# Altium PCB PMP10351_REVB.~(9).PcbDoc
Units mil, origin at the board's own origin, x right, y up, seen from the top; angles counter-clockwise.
Board outline 2350 x 1500 mil, 2 copper layers (Top Layer, Bottom Layer), stack 62 mil thick; 34 components, 23 nets, 80 pads, 5 vias.
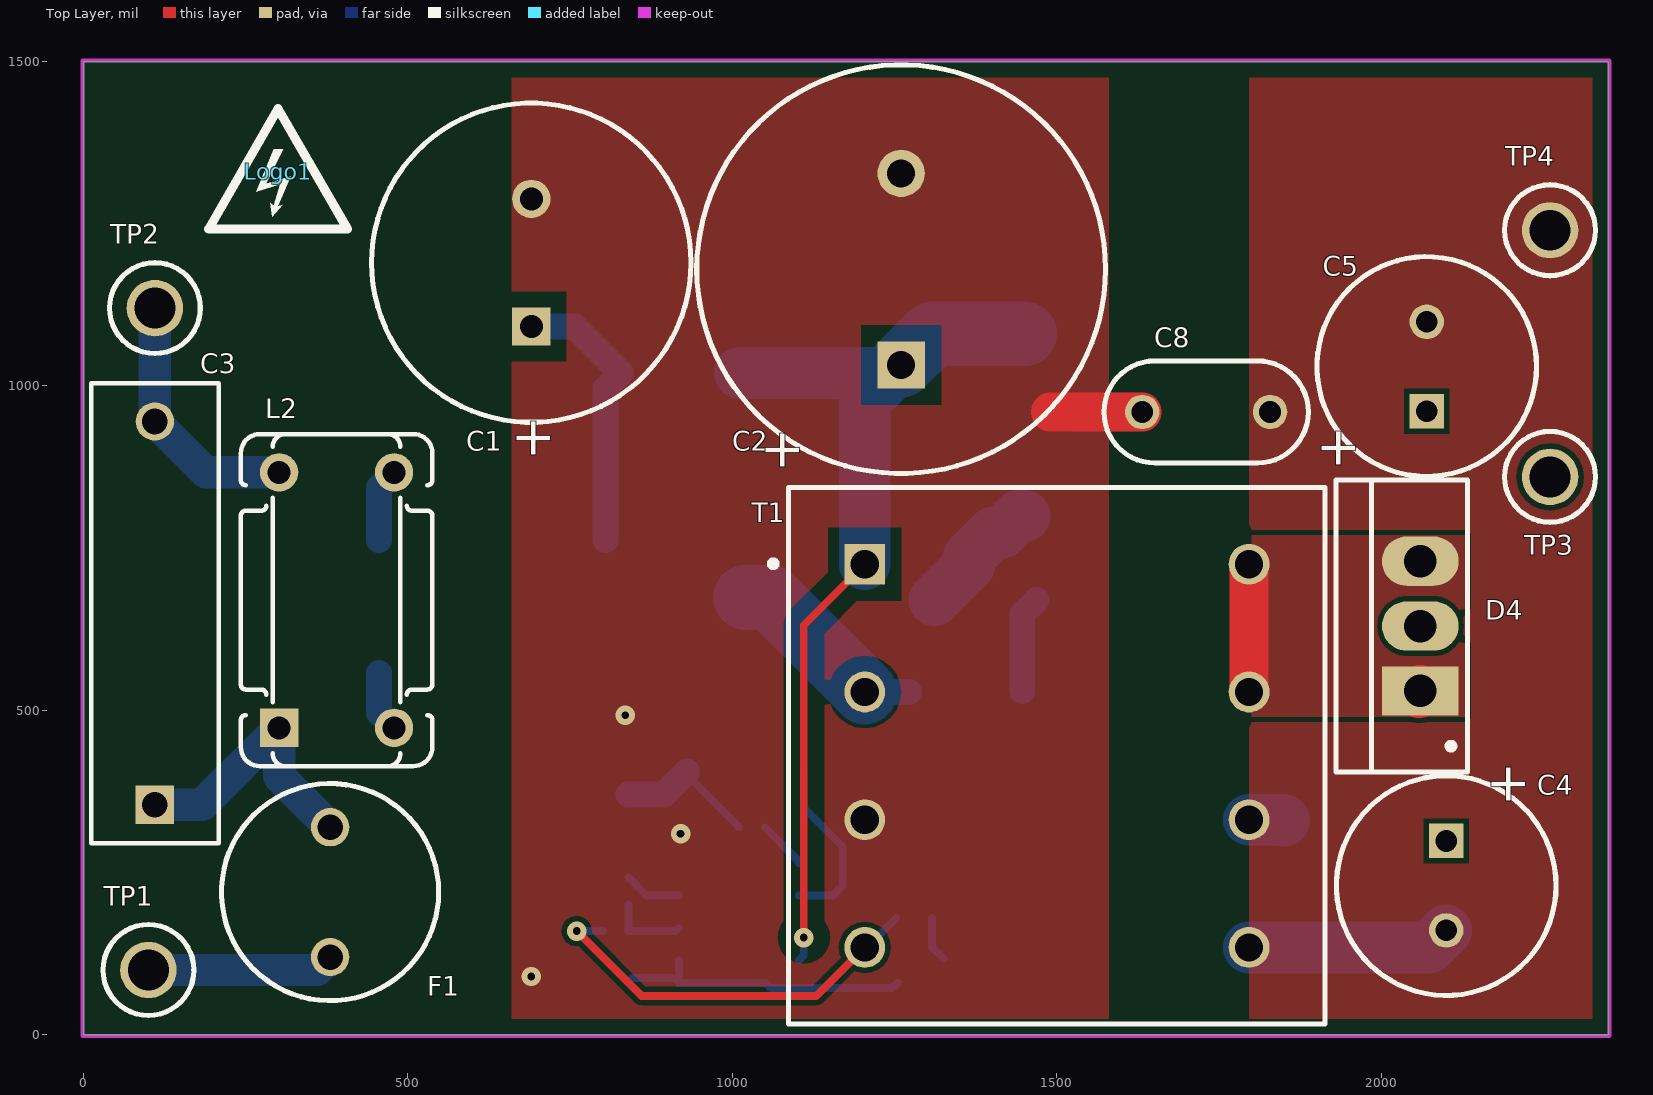
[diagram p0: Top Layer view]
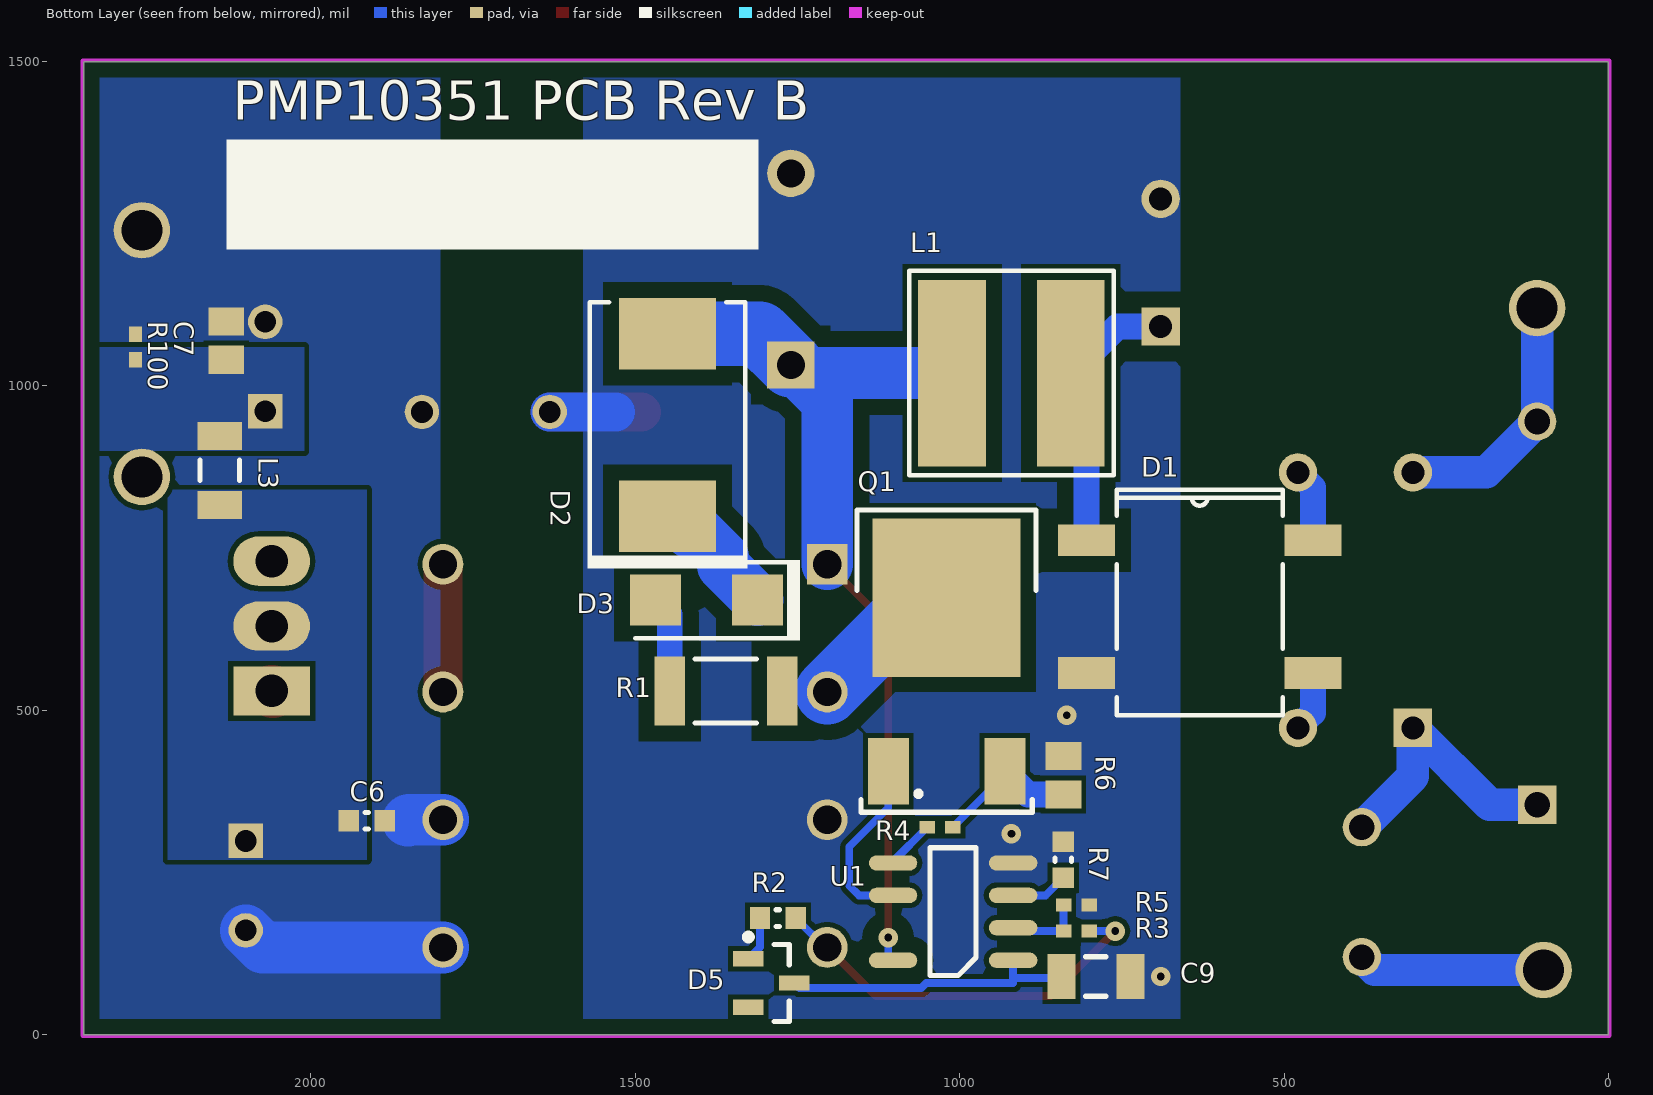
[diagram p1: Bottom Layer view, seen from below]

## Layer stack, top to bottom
Top Solder: solder mask 0.4, Solder Resist, Dk 3.5
Top Layer: signal copper 1.4
Dielectric1: core 59.2, FR-4, Dk 4.8
Bottom Layer: signal copper 1.4
Bottom Solder: solder mask 0.4, Solder Resist, Dk 3.5

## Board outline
0,0 2350,0 2350,1500 0,1500

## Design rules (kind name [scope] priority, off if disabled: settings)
AcuteAngle [All] p1: minimum=1.00000000000000E+0000 checktracksonly=FALSE
AssemblyTestPointUsage [All] p1: valid=2
Clearance "Schematic Clearance Constraint_4" [InNet('NetC1_1')] p1: gap=25
Clearance "Schematic Clearance Constraint_3" [InNet('NetC2_1')] p2: gap=25
Clearance "Schematic Clearance Constraint_2" [InNet('NetD2_1')] p3: gap=25
Clearance "Schematic Clearance Constraint_1" [InNet('NetD3_2')] p4: gap=25
Clearance "Schematic Clearance Constraint" [InNet('NetQ1_4')] p5: gap=24
Clearance Clearance_Keepouts [((IsTrack Or IsArc) And Not InPoly) And IsFree and IsKeepOut vs ((IsTrack Or IsArc) And Not InPoly) And IsFree and IsKeepOut] p6: gap=0
Clearance Clearance_BoardEdge_MountingHoles [OnCopper and InComponentClass('Mounting Holes') vs IsKeepOut] p7: gap=25
Clearance Clearance_BoardEdge_Poly [OnCopper and InPoly vs IsKeepOut] p8: gap=25
Clearance Clearance_BoardEdge [OnCopper and Not InComponentClass('Logo') and not InComponentClass('FiducialMark') and not InRegion(1000,500,4000,800) and Not IsKeepout vs IsKeepOut] p9: gap=15
Clearance Clearance_Poly [InPolygon] p10: gap=8
Clearance [All] p11: gap=7.87
ComponentClearance ComponentClearance_MountingHoles_FiducialMarks [InComponentClass('Mounting Holes') vs InComponentClass('FiducialMark')] p1: gap=15 collisioncheckmode=3 verticalgap=10 showdistances=FALSE
ComponentClearance ComponentClearance_Shunt [InComponentClass('Header') vs InComponentClass('Shunt')] p2: gap=0 collisioncheckmode=3 verticalgap=0 showdistances=FALSE
ComponentClearance ComponentClearance_Logo [InComponentClass('Logo')] p3: gap=15 collisioncheckmode=3 verticalgap=10 showdistances=FALSE
ComponentClearance ComponentClearance_ScrewToNut [(HasFootprint('NY PMS 440 0025 PH')) vs (HasFootprint('Keystone_1902C'))] p4: gap=5 collisioncheckmode=3 verticalgap=10 showdistances=FALSE
ComponentClearance ComponentClearance_MountingHoles [InComponentClass('Mounting Holes')] p5: gap=15 collisioncheckmode=3 verticalgap=100000 showdistances=FALSE
ComponentClearance ComponentClearance_SmallPassives [HasFootprint('0201*') or HasFootprint('0402*') or HasFootprint('0508') or HasFootprint('0603*') or HasFootprint('0612') or HasFootprint('0805*') or HasFootprint('0815*') or HasFootprint('0830*') or HasFootprint('1206*') or HasFootprint('1210*') or HasFootprint('1808*') or HasFootprint('1812*') or HasFootprint('1825*') or HasFootprint('2010*') or HasFootprint('2220*') or HasFootprint('2225*') or HasFootprint('2512*') or HasFootprint('2728*') or HasFootprint('3518*') vs HasFootprint('0201*') or HasFootprint('0402*') or HasFootprint('0508') or HasFootprint('0603*') or HasFootprint('0612') or HasFootprint('0805*') or HasFootprint('0815*') or HasFootprint('0830*') or HasFootprint('1206*') or HasFootprint('1210*') or HasFootprint('1808*') or HasFootprint('1812*') or HasFootprint('1825*') or HasFootprint('2010*') or HasFootprint('2220*') or HasFootprint('2225*') or HasFootprint('2512*') or HasFootprint('2728*') or HasFootprint('3518*')] p6: gap=15 collisioncheckmode=3 verticalgap=10 showdistances=FALSE
ComponentClearance ComponentClearance_THtoSMT [IsThruComponent vs IsSMTComponent] p7: gap=15 collisioncheckmode=3 verticalgap=30 showdistances=FALSE
ComponentClearance ComponentClearance_THtoTH [IsThruComponent vs IsThruComponent] p8: gap=15 collisioncheckmode=3 verticalgap=30 showdistances=FALSE
ComponentClearance [All] p9: gap=15 collisioncheckmode=3 verticalgap=10 showdistances=FALSE
DiffPairsRouting [All] p1: maxlimit=100 minlimit=10 mostfreqgap=10 toplayer_minwidth=15 toplayer_maxwidth=15 toplayer_prefwidth=15 bottomlayer_minwidth=15 bottomlayer_maxwidth=15 bottomlayer_prefwidth=15 maxuncoupledlength=1000
FabricationTestPointUsage TestPointUsage [All] p1: valid=2 allowmultiple=FALSE
FabricationTestpoint Testpoint [All] p1: side=3 testpointundercomponent=TRUE minsize=40 maxsize=100 preferedsize=60 minholesize=0 maxholesize=40 preferedholesize=32 testpointgrid=1 allowsidetop=TRUE allowsidebottom=TRUE usegrid=TRUE gridtolerance=0.01
FanoutControl Fanout_LCC [IsLCC] p1: bgadir=Out bgaviamode=Centered fanoutstyle=Auto fanoutdirection=Alternating viagrid=1 // Fanout_LCC (Default Rule)
FanoutControl Fanout_BGA [IsBGA] p2: bgadir=Out bgaviamode=Centered fanoutstyle=Auto fanoutdirection=Alternating viagrid=1 // Fanout_BGA (Default Rule)
FanoutControl Fanout_Default [All] p4: bgadir=Out bgaviamode=Centered fanoutstyle=Auto fanoutdirection=Alternating viagrid=1 // Fanout_Default (Default Rule)
FanoutControl Fanout_Small [(CompPinCount < 5)] p5: bgadir=Out bgaviamode=Centered fanoutstyle=Auto fanoutdirection=OutThenIn viagrid=1 // Fanout_Small (Default Rule)
HoleSize [All] p1: absolutevalues=TRUE maxlimit=251 minlimit=8 maxpercent=80.000 minpercent=20.000
MinimumAnnularRing MinimumAnnularRing_ThermalPadVias [IsVia and InAnyComponent] p1: minimumring=5.91
MinimumAnnularRing [All] p2: minimumring=9
MinimumSolderMaskSliver MinimumSolderMaskSliver_Logo [InComponentClass('Logo') vs InComponentClass('Logo')] p1: minsoldermaskwidth=0.7
MinimumSolderMaskSliver [All] p2: minsoldermaskwidth=0
PlaneConnect [All] p1: planeconnectstyle=Relief reliefexpansion=10 reliefentries=4 reliefconductorwidth=10 reliefairgap=10
PolygonConnect [All] p1: connectstyle=Direct reliefconductorwidth=10 reliefentries=4 polygonreliefangle="90 Angle" airgapwidth=10
RoutingVias ThermalPadVias [IsVia and InAnyComponent] p1: holewidth=7.87 width=19.68 viastyle="Through Hole" minholewidth=7.87 minwidth=19.68 maxholewidth=12.99 maxwidth=23.62
RoutingVias [All] p2: holewidth=16 width=34 viastyle="Through Hole" minholewidth=7.87 minwidth=26 maxholewidth=40 maxwidth=65
SilkToBoardRegionClearance [Not ((IsComment or IsDesignator) And (Hide <> 'False')) and not InRegion(1000,500,4000,800)] p1:
SilkToSilkClearance SilkToSilkClearance_Pb-FreeLogo [(HasFootprint('Pb-Free_Overlay_Medium') OR HasFootprint('Pb-Free_Overlay_Small')) vs (HasFootprint('Pb-Free_Overlay_Medium') OR HasFootprint('Pb-Free_Overlay_Small'))] p1: silktosilkclearance=0
SilkToSilkClearance [All] p2: silktosilkclearance=0
SilkToSolderMaskClearance "Silk to Solder Mask Opening" [All] p1: minsilkscreentomaskgap=0 clearancetoexposedcopper=FALSE
SolderMaskExpansion [All] p1: expansion=1.97
UnpouredPolygon [All] p1: allowunpoured=FALSE
Width [All] p1: maxlimit=100 minlimit=6 preferedwidth=10 checkconnectedcopper=TRUE
14 further rules are at their usual default settings.

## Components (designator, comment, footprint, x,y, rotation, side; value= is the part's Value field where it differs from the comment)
C1 "EEUED2G150" CAPPR5-12.5X20 690,1190 r90 top
C2 "EEUED2G330S" CAPPR7.5-16X20 1260,1180 r90 top
C3 "B32922C3104M" B32922_10.5mm 110,650 r90 top
C4 "16ZLG470MEFC8X16" ZLG_800x1600 2100,230 r270 top
C5 "16ZLG470MEFC8X16" ZLG_800x1600 2070,1030 r90 top
C6 "GRM188R61E105KA12D" 0603L 1913.39,330 r180 bottom
C7 "GRM21BR61E106MA73" 0805L 2130,1070 r90 bottom
C8 "DE2E3KY222MA2BM01" CAPRD500W60D800H850 1730,960 r180 top
C9 "GRM319R61H475KA12" 1206L 790,90 r180 bottom
D1 "DF1506S-T" DF-S 630,660 r180 bottom
D2 "SMCJ100A" SMC 1450,940 r90 bottom
D3 "MURA160T3G" SMA 1390,670 r0 bottom
D4 "VF40100C-E3/4W" TO-220AB 2060,630 r90 top
D5 "BAS21-TP" SOT-23L 1290,80 r180 bottom
F1 "37212000001" FUSE_372 380,220 r270 top
L1 "CDRH6D28NP-330NC" CDRH6D28 920,1020 r0 bottom
L2 "744821240" WE-CMB_XS 390,670 r90 top
L3 "HI1206T500R-10" 1206L 2140,870 r90 bottom
Logo1 "DANGER HIGH VOLTAGE" IEC_HighVoltage_Small 300,1330 r0 top
Q1 "TK5P60W_RVQ" DPAK 1020,540 r90 bottom
R1 "CRCW201024R0JNEF" 2010L 1360,530 r0 bottom
R2 "CRCW060320R0JNEA" 0603L 1280,180 r0 bottom
R3 "CRCW040282K5FKED" 0402L 820,160 r180 bottom
R4 "CRCW04021K00FKED" 0402L 1030,320 r0 bottom
R5 "CRCW040223K7FKED" 0402L 820,200 r0 bottom
R6 "CRM0805-FX-R510ELF" 0805L 840,400 r270 bottom
R7 "N/A" 0603L 840,270 r270 bottom
R100 "CRCW04024K99FKED" 0402L 2270,1060 r90 bottom
T1 "G144071LF" GCI_G144071LF 1500,430 r0 top
TP1 "5012" Keystone5012 100,100 r0 top
TP2 "5012" Keystone5012 110,1120 r0 top
TP3 "5010" Keystone5010 2260,860 r0 top
TP4 "5011" Keystone5011 2260,1240 r0 top
U1 "UCC28713D" D0007A_L 1010,190 r0 bottom

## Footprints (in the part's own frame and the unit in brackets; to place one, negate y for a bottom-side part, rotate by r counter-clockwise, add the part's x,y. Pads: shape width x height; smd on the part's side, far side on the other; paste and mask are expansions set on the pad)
0402L [mm] "0402 from SM-752 data"
  rect 0.6x0.5 smd: 1(-0.5,0) 2(0.5,0)
  body extent -0.55,-0.3 0.55,0.3, height 0.6
0603L [mm] "0603 from SM-752 data"
  rect 0.8x0.85 smd: 1(-0.7,0) 2(0.7,0)
  silkscreen extent -0.07,-0.33 0.07,0.33, body extent -0.87,-0.47 0.87,0.47, height 0.85
0805L [mm] "0805 from SM-752 data"
  rect 1.1x1.4 smd: 1(-0.75,0) 2(0.75,0)
  body extent -1.1,-0.72 1.1,0.72, height 1.1
1206L [mm] "1206 from SM-752 data"
  rect 1.1x1.75 smd: 1(-1.35,0) 2(1.35,0)
  silkscreen extent -0.4,-0.77 0.4,0.77, body extent -1.7,-0.9 1.7,0.9, height 1.35
2010L [mm]
  rect 1.2x2.7 smd: 1(-2.2,0) 2(2.2,0)
  silkscreen extent -1.2,-1.25 1.2,1.25, body extent -2.73,-1.45 2.73,1.45, height 1.66
B32922_10.5mm [mm] "Epcos film capacitors, 15mm spacing"
  rect 1.5x1.5 hole 1: 1(-7.5,0)
  round 1.5 hole 1: 2(7.5,0)
  silkscreen extent -9,-2.5 9,2.5, body extent -9,-2.5 9,2.5, height 10.5
CAPPR5-12.5X20 [mm] "Capacitor, Electrolytic, Radial; Body 12.5 x 20 mm (Dia.xH typ); Pin Spacing 5 mm (typ)"
  rect 1.5x1.5 hole 0.9: 1(-2.5,0)
  round 1.5 hole 0.9: 2(2.5,0)
  silkscreen extent -6.25,-6.25 6.25,6.25, body extent -6.01,-6.01 6.01,6.01, height 22
CAPPR7.5-16X20 [mm] "Capacitor, Electrolytic, Radial; Body 16 x 20 mm (Dia.xH typ); Pin Spacing 7.5 mm (typ)"
  rect 1.85x1.85 hole 1.1: 1(-3.75,0)
  round 1.85 hole 1.1: 2(3.75,0)
  silkscreen extent -8,-8 8,8, body extent -8.01,-8.01 8.01,8.01, height 22
CAPRD500W60D800H850 [mm] "RADIAL CAPACITOR"
  round 1.35 hole 0.85: 1(-2.5,0) 2(2.5,0)
  silkscreen extent -4,-2 4,2, body extent -3.97,-2.5 4,2.5, height 10.99
CDRH6D28 [mm] "Sumida reommended land pattern"
  rect 2.65x7.3 smd: 1(-2.325,0) 2(2.325,0)
  silkscreen extent -4,-4 4,4, body extent -3.5,-3.5 3.5,3.5, height 3
D0007A_L [mm] "SOIC, 7-Leads, Body 4.9x3.9mm, Pitch 1.27mm, IPC High Density"
  oval 1.9x0.6 smd: 1(-2.35,1.905) 2(-2.35,0.635) 3(-2.35,-0.635) 4(-2.35,-1.905) 5(2.35,-1.905) 6(2.35,-0.635) 8(2.35,1.905)
  silkscreen extent -0.9,-2.5 0.9,2.5, body extent -3,-2.5 3,2.5, height 1.54
DF-S [mil] "Diodes Inc. recommended land pattern per ap02001.pdf rev 30"
  rect 88x49 smd: 1(-174.5,102.36) 2(-174.5,-102.36) 3(174.5,-102.36) 4(174.5,102.36)
  silkscreen extent -128,-168 128,180, body extent -205,-168 205,168, height 108
DPAK [mm] "D-PAK, 3-Pads, Body 6.22x6.73mm (max), TO-252AA using nominal STEP model"
  rect 2.6x1.6 smd: 1(-3.4,2.28) 3(-3.4,-2.28)
  rect 6.2x5.8 smd paste-2.9: 4(3.4,0)
  silkscreen extent -5,-3.5 6.83,3.5, body extent -3.86,-3.29 5.84,3.29, height 2.48
FUSE_372 [mm] "LITTELFUSE"
  round 1.5 hole 1: 1(-2.54,0) 2(2.54,0)
  silkscreen extent -4.25,-4.25 4.25,4.25, body extent -4.26,-4.26 4.26,4.26, height 8
GCI_G144071LF [mm] "THD, 8-Leads, Body 21x21mm, Pitch 5mm"
  rect 1.6x1.6 hole 1.1: 1(-7.52,7.5)
  round 1.6 hole 1.1: 2(-7.52,2.5) 3(-7.52,-2.5) 4(-7.52,-7.5) 5(7.52,-7.5) 6(7.52,-2.5) 7(7.52,2.5) 8(7.52,7.5)
  silkscreen extent -11.22,-10.5 10.5,10.5, body extent -10.5,-10.5 10.5,10.5, height 16.5
IEC_HighVoltage_Small [mil]
  silkscreen extent -107,-88 107,97
Keystone5010 [mil] "Keystone Multipurpose loops"
  round 87 hole 63: 1(0,0)
  silkscreen extent -70,-70 70,70, body extent -63,-63 63,62, height 319
Keystone5011 [mil] "Keystone Multipurpose loops"
  round 87 hole 63: 1(0,0)
  silkscreen extent -70,-70 70,70, body extent -63,-63 63,62, height 319
Keystone5012 [mil] "Keystone Multipurpose loops"
  round 87 hole 63: 1(0,0)
  silkscreen extent -70,-70 70,70, body extent -63,-63 63,62, height 319
SMA [mm] "Molded Diode, 2-Leads, Body 4.3x2.6mm, IPC Medium Density, based on OnSemi component dimensions and land pattern"
  rect 2x2 smd: 1(-2,0) 2(2,0)
  silkscreen extent -3.66,-1.57 2.79,1.57, body extent -2.6,-1.3 2.6,1.3, height 2.42
SMC [mil] "Molded Diode, 2-Leads, Body 6.9x5.8mm, IPC Medium Density, based on OnSemi component dimensions and land patterns"
  rect 110x150 smd: 1(-140.49,0) 2(140.49,0)
  silkscreen extent -221,-123 189,124, body extent -156,-116 156,116, height 91
SOT-23L [mm] "SOT23, 3-Leads, Body 2.9x1.3mm, Pitch 0.95mm, Lead Span 2.5mm, IPC High Density"
  rect 1.2x0.6 smd: 1(-0.9,0.95) 2(-0.9,-0.95) 3(0.9,0)
  silkscreen extent -1.02,-1.5 0.7,1.92, body extent -1.16,-1.45 1.21,1.45, height 1
TO-220AB [mil] "Copied from Altium's version of TO3B"
  rect 76x118.11 hole 50: 1(-100,0)
  oval 76x118.11 hole 50: 2(0,0) 3(100,0)
  silkscreen extent -225,-73 225,130, body extent -221,-59 221,126, height 765
WE-CMB_XS [mm] "WE-CMB Series Size XS"
  rect 1.5x1.5 hole 0.9: 1(-5,2.25)
  round 1.5 hole 0.9: 2(-5,-2.25) 3(5,-2.25) 4(5,2.25)
  silkscreen extent -6.5,-3.75 6.5,3.75, body extent -6.5,-3.75 6.5,3.75, height 16.24
ZLG_800x1600 [mm] "TH, 2-Leads, Body 8x16mm"
  rect 1.35x1.35 hole 0.85: 1(-1.75,0)
  round 1.35 hole 0.85: 2(1.75,0)
  silkscreen extent -4.3,-4.3 4.3,4.3, body extent -4.22,-4.34 4.24,4.14, height 17.51

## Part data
C1: "CAP, AL, 15uF, 400V, +/-20%, 1.909859 ohm, TH"
C2: "CAP, AL, 33 µF, 400 V, +/- 20%, 0.868117 ohm, TH"
C3: "CAP, Film, 0.1 µF, 630 V, +/- 20%, TH"
C4 C5: "CAP, AL, 470 µF, 16 V, +/- 20%, 0.028 ohm, TH"
C6: "CAP, CERM, 1 µF, 25 V, +/- 10%, X5R, 0603"
C7: "CAP, CERM, 10 µF, 25 V, +/- 20%, X5R, 0805"
C8: "CAP, CERM, 2200pF, 250V, +/-20%, KY, Radial D8x5mm"
C9: "CAP, CERM, 4.7 µF, 50 V, +/- 10%, X5R, 1206"
D1: "Diode, Switching-Bridge, 600V, 1.5A, DF-S"
D2: "Diode, TVS, Uni, 100V, 1500W, SMC"
D3: "Diode, Ultrafast, 600V, 1A, SMA"
D4: "Diode, Schottky, 100V, 20A, TH"
D5: "Diode, P-N, 200V, 200A, SOT-23"
F1: library part 37215000001, "Fuse, 2A, 250V, TH"
L1: "Inductor, Shielded Drum Core, Ferrite, 33uH, 0.97A, 0.165 ohm, SMD"
L2: "Coupled inductor, 4000uH, 1.5A, 0.14 ohm, +/-30%, TH"
L3: "Ferrite Bead, 50 ohm @ 100MHz, 6A, 1206"
Logo1: library part IEC_HighVoltage, "IEC 61010-1 High Voltage Warning"
Q1: "MOSFET, N-CH, 600V, 5.4A, DPAK"
R1: "RES, 24 ohm, 5%, 0.75W, 2010"
R2: "RES, 20, 5%, 0.1 W, 0603"
R3: "RES, 82.5 k, 1%, 0.063 W, 0402"
R4: "RES, 1.00 k, 1%, 0.063 W, 0402"
R5: "RES, 23.7 k, 1%, 0.063 W, 0402"
R6: "RES, 0.51 ohm, 1%, 0.25W, 0805"
R7: library part CRCW06030000Z0EA, "Do Not Populate"
R100: "RES, 4.99 k, 1%, 0.063 W, 0402"
T1: "Transformer, 400 uH, TH"
TP1 TP2: "Test Point, Multipurpose, White, TH"
TP3: "Test Point, Multipurpose, Red, TH"
TP4: "Test Point, Multipurpose, Black, TH"
U1: "Constant-Voltage, Constant-Current Controller With Primary-Side Regulation, D0007A"

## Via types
v1: diameter 30, hole 12, Top Layer to Bottom Layer, 5 vias

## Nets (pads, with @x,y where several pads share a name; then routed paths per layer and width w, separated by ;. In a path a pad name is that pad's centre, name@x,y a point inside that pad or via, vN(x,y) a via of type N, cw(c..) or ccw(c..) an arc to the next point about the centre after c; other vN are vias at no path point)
GND: C4.2 C5.2 C6.2 C7.2 C8.1 R100.2 T1.5 T1.6 TP4.1 | length 369.5
  Bottom Layer w80: T1.5 2073.62,134.72 C4.2 ; T1.6 1848.43,331.57 1850,330
NetC1_1: C1.1 D1.1 L1.1 | length 435.7
  Bottom Layer w40: C1.1 756.89,1091.57 L1.1 804.5,996.04 D1.1
NetC2_1: C2.1 D2.2 L1.2 T1.1 U1.8 | length 1428.6
  Top Layer w12: v1(1110,150) 1110,631.34 T1.1
  Bottom Layer w12: U1.8 1110,122.48 v1(1110,150)
  Bottom Layer w50: C2.1@1247.64,1020 C2.1
  Bottom Layer w80: L1.2 1247.64,1020 1203.94,976.3 T1.1
  Bottom Layer w100: C2.1 1308.13,1080.49 D2.2
NetC3_1: C3.1 F1.1 L2.1 | length 426.2
  Bottom Layer w50: C3.1 182.99,354.72 L2.1 301.42,398.58 F1.1
NetC3_2: C3.2 L2.4 TP2.1 | length 398.6
  Bottom Layer w50: TP2.1 C3.2 188.43,866.85 L2.4
NetC4_1: C4.1 C6.1 D4.2 L3.1
NetC5_1: C5.1 C7.1 L3.2 R100.1 TP3.1
NetC9_1: C9.1 D5.3 U1.1 | length 450.4
  Bottom Layer w12: C9.1@845.67,87.48 917.48,87.48 ; U1.1 917.48,87.48 ; D5.3 1246.76,72.19 1059.2,72.19 1051.39,80 917.48,80 917.48,87.48
NetD1_3: D1.3 L2.2 | length 94
  Bottom Layer w40: D1.3 455.5,496.23 L2.2
NetD1_4: D1.4 L2.3 | length 114
  Bottom Layer w40: D1.4 455.5,843.77 L2.3
NetD2_1: D2.1 D3.1 | length 200.1
  Bottom Layer w80: D3.1 1364.37,723.11 1364.37,736.29 1402.45,774.37 1415.63,774.37 1440.77,799.51 D2.1
NetD3_2: D3.2 R1.2 | length 149.2
  Bottom Layer w40: R1.2 1446.61,647.87 D3.2
NetD4_1: D4.1 D4.3 T1.7 T1.8 | length 199.1
  Top Layer w60: T1.7 T1.8
  Top Layer w80: D4.1@2058.43,528.43 D4.1
NetD5_1: D5.1 R2.2 | length 70
  Bottom Layer w12: R2.2 1307.56,135.28 D5.1
NetF1_2: F1.2 TP1.1 | length 288.3
  Bottom Layer w50: TP1.1 360,100 F1.2
NetQ1_1: Q1.1 U1.6 | length 274.8
  Bottom Layer w12: U1.6 1155,215 1170,230 1170,290 1109.76,350.24 Q1.1
NetQ1_3: Q1.3 R4.1 R6.2 | length 224.3
  Bottom Layer w12: Q1.3 930.24,400.08 R4.1
  Bottom Layer w40: R6.2 894.57,370.47 Q1.3
NetQ1_4: Q1.4 R1.1 T1.2 | length 312.1
  Bottom Layer w40: T1.2 R1.1@1271.81,528.43
  Bottom Layer w100: Q1.4 1058.5,673.86 T1.2
NetR2_1: R2.1 R3.2 T1.4 | length 623.9
  Top Layer w12: v1(760,160) 860,60 1129.21,60 T1.4
  Bottom Layer w12: v1(760,160) R3.2 ; T1.4 1207.17,134.72 R2.1
NetR3_1: R3.1 R5.2 U1.2 | length 119.9
  Bottom Layer w12: R5.2 R3.1 912.48,160 U1.2
NetR4_2: R4.2 U1.5 | length 76.9
  Bottom Layer w12: R4.2 1102.52,267.17 U1.5
NetR7_2: R7.2 U1.3 | length 88.8
  Bottom Layer w12: R7.2 867.44,215 U1.3
PGND: C1.2 C2.2 C8.2 C9.2 D1.2 R5.1 R6.1 R7.1 T1.3 U1.4 | length 243.1
  Top Layer w60: 1490,960 C8.2
  Bottom Layer w60: 1530,960 C8.2
  other v1: 690,90 920,310 834.73,492.48
pads on no net: D5.2

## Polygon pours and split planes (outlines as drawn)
NetD4_1 on Top Layer "Top Layer-D4" (solid, remove dead copper, pour order 10): 1800,770 2130,770 2130,490 1800,490
GND on Top Layer "Top Layer-GND" (solid, remove dead copper, pour order 11): 1796.07,10 2340,10 2340,1500 1796.07,1500
PGND on Top Layer "Top Layer-PGND" (solid, remove dead copper, pour order 12): 660,10 1580,10 1580,1490 660,1490
GND on Bottom Layer "Bottom Layer-GND" (solid, remove dead copper, pour order 15): 1800,1500 1800,10 2340,10 2340,1500
NetC5_1 on Bottom Layer "Bottom Layer-VOUT" (solid, remove dead copper, pour order 14): 2010,1060 2010,900 2340,900 2340,1060
NetC4_1 on Bottom Layer "Bottom Layer-VOUT1" (solid, remove dead copper, pour order 13): 1913.39,840 1913.39,270 2220,270 2220,840
PGND on Bottom Layer "Bottom Layer-PGND" (solid, remove dead copper, pour order 9): 660,20 1579.92,20 1579.92,1500 660,1500

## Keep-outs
Keep-Out Layer:
  lines w5: -2.5,0 ccw(c0,0) 0,-2.5 ; -2.5,0 ccw(c0,0) 0,-2.5 ; -2.5,0 -2.5,1500 ; -2.5,1500 cw(c0,1500) 0,1502.5 ; -2.5,1500 cw(c0,1500) 0,1502.5 ; 0,-2.5 2350,-2.5 ; 0,1502.5 2350,1502.5 ; 2350,-2.5 ccw(c2350,0) 2352.5,0 ; 2350,-2.5 ccw(c2350,0) 2352.5,0 ; 2350,1502.5 cw(c2350,1500) 2352.5,1500 ; 2350,1502.5 cw(c2350,1500) 2352.5,1500 ; 2352.5,0 2352.5,1500
  text ".Layer_Name" at 577,-858.49 h60

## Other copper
Top Layer:
  text ".Layer_Name" at 577,-858.49 h60
Bottom Layer:
  text ".Layer_Name" at 577,-858.49 h60

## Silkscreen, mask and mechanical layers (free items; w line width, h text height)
Top Overlay:
  text ".Layer_Name" at 577,-858.49 h60
Bottom Overlay:
  rectangle: 1310,1210 2130,1380
  text "PMP10351 PCB Rev B" at 2120,1410 h60
  text ".Layer_Name" at 577,-858.49 h60
Top Paste:
  text ".Layer_Name" at 577,-858.49 h60
Bottom Paste:
  text ".Layer_Name" at 577,-858.49 h60
Top Solder:
  text ".Layer_Name" at 577,-858.49 h60
  text ".Layer_Name" at 577,-858.49 h60
Bottom Solder:
  text ".Layer_Name" at 577,-858.49 h60
Drill Guide:
  text ".Layer_Name" at 577,-858.49 h60
M1 Board Outline:
  the board outline again, w10
  text ".Layer_Name" at 577,-858.49 h60
M2 Board Dimensions:
  rectangle: 0,-285.5 125,-160.5
  rectangle: 125,-410.5 500,-285.5
  lines w7: 0,-285.5 1000,-285.5 ; 125,-410.5 125,-160.5 ; 250,-410.5 250,-160.5 ; 500,-410.5 500,-160.5 ; 750,-410.5 750,-160.5 ; 0,-410.5 1000,-410.5 1000,-160.5 0,-160.5 0,-410.5
  text ".Layer_Name" at 577,-858.49 h60
M3 3D STEP Top:
  text ".Layer_Name" at 577,-858.49 h60
M4 3D STEP Bottom:
  text ".Layer_Name" at 577,-858.49 h60
M5 Assembly Top:
  lines w10: -292,-930.17 6308,-930.17 ; -292,-726.83 6310,-726.83 ; -292,-523.5 -292,-1133.5 3713,-1133.5 6310,-1133.5 6310,-523.5 -291.5,-523.5 -291.5,-1133.5 1284,-1133.5 ; 2173,-1133.5 2173,-523.5 ; 3440,-726.83 3440,-523.5 ; 4280,-726.83 4280,-523.5 ; 4902,-1140 4902,-937.17
  text "COMPONENTS MARKED 'DNP' SHOULD NOT BE POPULATED." at 1153.5,-318.5 h60
  text "ASSEMBLY VARIANT:" at 1153,-434 h60
  text ".VariantName" at 2189,-434 h60
  text "PCB VIEWED FROM TOP SIDE" at -228.5,-655.67 h60
  text "BOARD #:" at 2248,-655.67 h60
  text ".PRJ_Number" at 2793.5,-655.67 h60
  text "REV:" at 3638,-655.67 h60
  text ".PCB_Rev" at 3929.5,-655.67 h60
  text "SVN REV:" at 4476,-655.67 h60
  text ".VersionControl_RevNumber" at 4982,-655.67 h60
  text "IGNORE ->" at -228.5,-858.49 h60
  text "PLOT NAME =" at -228.5,-1064.34 h60
  text ".plot_File_Name" at 577,-1064.34 h60
  text "GENERATED    :" at 2250,-1064.34 h60
  text ".Print_Date" at 3119.5,-1064.34 h60
  text ".Print_Time" at 3848.5,-1064.34 h60
  text "TEXAS INSTRUMENTS" at 5113,-1064.34 h60
M6 Assembly Bottom:
  lines w10: -292.5,-727.33 6309.5,-727.33 ; -290.5,-930.67 6309.5,-930.67 ; 1115.5,-1140.5 1115.5,-937.67 ; 1737.5,-727.33 1737.5,-524 ; 2577.5,-727.33 2577.5,-524 ; 3844.5,-1134 3844.5,-524 ; 4733.5,-1134 6309,-1134 6309,-524 -292.5,-524 -292.5,-1134 2304.5,-1134 6309.5,-1134 6309.5,-524
  text "COMPONENTS MARKED 'DNP' SHOULD NOT BE POPULATED." at 6102,-318 h60
  text ".VariantName" at 5058,-434 h60
  text "ASSEMBLY VARIANT:" at 6097,-434 h60
  text ".VersionControl_RevNumber" at 1035.5,-656.17 h60
  text "SVN REV:" at 1541.5,-656.17 h60
  text ".PCB_Rev" at 2088,-656.17 h60
  text "REV:" at 2379.5,-656.17 h60
  text ".PRJ_Number" at 3224,-656.17 h60
  text "BOARD #:" at 3769.5,-656.17 h60
  text "PCB VIEWED FROM BOTTOM SIDE" at 6246,-656.17 h60
  text "IGNORE ->" at 2547.85,-858.49 h60
  text "TEXAS INSTRUMENTS" at 904.5,-1064.84 h60
  text ".Print_Time" at 2169,-1064.84 h60
  text ".Print_Date" at 2898,-1064.84 h60
  text "GENERATED    :" at 3767.5,-1064.84 h60
  text ".plot_File_Name" at 5440.5,-1064.84 h60
  text "PLOT NAME =" at 6246,-1064.84 h60
M9 Title Sheet:
  drawing of 57 lines, arcs and shapes, not listed
  text "1" at 739.84,8036.5 h70
  text "2" at 3235.5,8036.5 h70
  text "3" at 5724.84,8036.5 h70
  text "4" at 8231.51,8036.5 h70
  text "5" at 10730.5,8036.5 h70
  text "6" at 13235.5,8036.5 h70
  text "A" at -416.5,6893.5 h70
  text "A" at 14383.5,6893.5 h70
  text "B" at -416.5,4513.5 h70
  text "B" at 14383.5,4513.5 h70
  text "C" at -416.5,2138.5 h70
  text "C" at 14383.5,2138.5 h70
  text "PROJECT TITLE:" at 11343.5,277.5 h45
  text ".PRJ_Title" at 11393.5,144.17 h70
  text "DESIGNED FOR:" at 11343.5,-23.5 h45
  text ".PRJ_Customer" at 11393.5,-163.5 h70
  text "D" at -416.5,-231.5 h70
  text "D" at 14383.5,-231.5 h70
  text "FILE NAME:" at 11343.5,-323.5 h45
  text ".PCB_File_Name_No_Path" at 11393.5,-443.5 h70
  text "Texas Instruments (TI) and/or its licensors do not warrant the accuracy or completeness of this specification" at 6374,-605.34 h45
  text "ENGINEER:" at 11343.5,-613.5 h45
  text "LAYOUT BY:" at 12848.5,-613.5 h45
  text "or any information contained therein. TI and/or its licensors do not warrant that this design will meet" at 6329.01,-718 h45
  text ".PRJ_Engineer" at 11393.5,-768.49 h70
  text ".PCB_Layout" at 12899,-768.49 h70
  text "the specifications, will be suitable for your application or fit for any particular purpose, or will operate in" at 6329.01,-830.67 h45
  text ".Layer_Name" at 577,-858.49 h60
  text "ALTIUM DESIGNER VERSION:" at 12848.5,-923.5 h45
  text "an implementation. TI and/or its licensors do not warrant that the design is production worthy. You should" at 6329.01,-943.33 h45
  text "completely validate and test your design implementation to confirm the system functionality for your application." at 6374,-1056 h45
  text ".print_Scale" at 11393.5,-1056.83 h70
  text ".Application_BuildNumber" at 12899,-1056.83 h70
  text "1" at 739.84,-1263.5 h70
  text "2" at 3235.5,-1263.5 h70
  text "3" at 5724.84,-1263.5 h70
  text "4" at 8231.51,-1263.5 h70
  text "5" at 10730.5,-1263.5 h70
  text "6" at 13235.5,-1263.5 h70
M10 Fab Notes:
  drawing of 185 lines, arcs and shapes, not listed
  text "DESIGN INFORMATION" at 12381.02,5910 h60
  text "MIN. TRACK WIDTH:" at 11736.46,5730 h60
  text "8" at 12832.7,5730 h60
  text "MIL" at 12987.46,5730 h60
  text "MIN. CLEARANCE:" at 11736.46,5598 h60
  text "0.2" at 12772.7,5598 h60
  text "mm" at 12987.46,5598 h60
  text "MIN. VIA PAD SIZE:" at 11736.46,5466 h60
  text "24" at 12802.71,5466 h60
  text "MIL" at 12987.46,5466 h60
  text "0.05mm (2MIL)" at 12431.46,5324.29 h60
  text "MINIMUM ANNULAR RING" at 11407.23,5320 h60
  text "EXTERNAL" at 13139.46,5320 h60
  text "PER" at 11607.23,5202 h60
  text "IPC-D-275 CLASS 2 LEVEL C" at 11827.23,5202 h60
  text "MIL, HOLES" at 13315.46,5089.71 h60
  text "+/-" at 12923,5089 h60
  text "+/-" at 13777,5089 h60
  text "REGISTRATION TOLERANCES:" at 11407.23,5084 h60
  text "METAL" at 12607,5084 h60
  text "5" at 13183.2,5084 h60
  text "3" at 14016.2,5084 h60
  text "MIL" at 14132.46,5084 h60
  text "MATERIAL:" at 11332.46,4874.54 h60
  text "FR-4 High Tg" at 12318.9,4734.21 h60
  text "FR-408" at 11753.46,4725.64 h60
  text "X" at 12165.46,4725.64 h60
  text "OTHER" at 13241.46,4725.64 h60
  text "62 MIL (1.6mm) +/-10%" at 12073.56,4562.92 h60
  text "THICKNESS:" at 11407.23,4558.64 h60
  text "X" at 11945.4,4558.64 h60
  text "OTHER" at 13358.46,4558.64 h60
  text "TOLERANCE:" at 11407.23,4400.64 h60
  text "X" at 12246.53,4400.64 h60
  text "ANSI IPC-6012 TYPE 3 CLASS 2" at 12433.48,4400.64 h60
  text "OTHER +/-" at 12433.46,4244.64 h60
  text "BOW & TWIST:" at 11407.23,4087.64 h60
  text "X" at 12246.53,4087.64 h60
  text "ANSI IPC-6012 TYPE 3 CLASS 2" at 12433.48,4087.64 h60
  text "OTHER +/-" at 12433.46,3929.13 h60
  text "DRILLING:" at 11332.46,3790.64 h60
  text "REFERENCE:" at 11407.23,3673.64 h60
  text "X" at 12055.46,3673.64 h60
  text "AS SHOWN" at 12242.46,3673.64 h60
  text "X" at 12956.46,3673.64 h60
  text "NC_DRILL FILES" at 13093.46,3673.64 h60
  text "PTH MIN COPPER THICKNESS:" at 11407.23,3515.64 h60
  text "X" at 12757.46,3515.64 h60
  text "1MIL" at 12894.46,3515.64 h60
  text "OTHER" at 13391.46,3515.64 h60
  text "BOARD FINISH:" at 11332.46,3356.64 h60
  text "SILKSCREEN:" at 11487.68,3238.64 h60
  text "X" at 12436.46,3238.64 h60
  text "TOP" at 12562.46,3238.64 h60
  text "X" at 12946.46,3238.64 h60
  text "BOTTOM" at 13073.46,3238.64 h60
  text "SILKSCREEN COLOR:" at 11487.68,3071.64 h60
  text "X" at 12435.42,3071.64 h60
  text "WHITE" at 12562.46,3071.64 h60
  text "OTHER" at 13073.46,3071.64 h60
  text "SOLDER RESIST COLOR:" at 11487.68,2901.64 h60
  text "X" at 12055.42,2742.44 h60
  text "GREEN" at 12182.46,2742.44 h60
  text "BLUE" at 12773.46,2742.44 h60
  text "OTHER" at 13311.46,2742.44 h60
  text "IMMERSION GOLD (ENIG)" at 12393.46,2553.92 h60
  text "ENEPIG" at 13731,2550.64 h60
  text "SURFACE FINISH:" at 11332.46,2549.64 h60
  text "X" at 11520,2400 h60
  text "IMM. TIN/SILVER OR EQUIV" at 11662,2392.64 h60
  text "OTHER" at 13093.46,2392.64 h60
  text "ARRAY/PANEL:" at 11332.46,2213.64 h60
  text "CUT AND TRIM PER MECH LAYER 1" at 12393.46,2209.35 h60
  text "N.C. ROUTE" at 12393.46,2057.64 h60
  text "X" at 13072.46,2057.64 h60
  text "V. SCORE" at 13259.46,2057.64 h60
  text "CERTIFICATION:" at 11332.46,1920.64 h60
  text "MATERIALS AND WORKMANSHIP FOR ALL PCBS" at 12057.46,1920.64 h60
  text "TO MEET OR EXCEED THE REQUIREMENTS OF:" at 12057.46,1822.64 h60
  text "X" at 11683.96,1686.13 h60
  text "ANSI IPC-A-600F CLASS ->" at 11822.96,1686.13 h60
  text "X" at 13462.02,1686.13 h60
  text "2" at 13580.96,1686.14 h60
  text "1" at 13265.96,1684.64 h60
  text "3" at 13934.96,1684.64 h60
  text "X" at 11686.02,1526.64 h60
  text "UL 94V-0" at 11822.96,1526.64 h60
  text "X" at 12498.02,1526.64 h60
  text "RoHS" at 12634.96,1526.64 h60
  text "OTHER" at 13279.36,1526.64 h60
  text "PER ORDER" at 13676.42,1526.64 h60
  text "ADDITIONAL REQUIREMENTS:" at 11332.46,1385.64 h60
  text "MICROSECTION:" at 11407.23,1270.64 h60
  text "YES" at 12312.96,1270.64 h60
  text "REQUIRED" at 13174.46,1114.49 h60
  text "BARE BOARD ELEC. TEST:" at 11407.23,1111.64 h60
  text "NONE" at 12712.96,1111.64 h60
  text "X" at 13047.46,1111.64 h60
  text "PER ORDER" at 13766.46,1111.64 h60
  text "MANUFACTURER'S UL:" at 11407.23,954.64 h60
  text "RAIL" at 12572.96,950.35 h60
  text "METAL" at 13064.77,950.35 h60
  text "X" at 13440,950 h60
  text "SILK" at 13576.46,950.35 h60
  text ".Layer_Name" at 577,-858.49 h60
M11 Gerber Information:
  lines w10: -292,-930.17 6308,-930.17 ; -292,-726.83 6310,-726.83 ; -292,-523.5 -292,-1133.5 3713,-1133.5 6310,-1133.5 6310,-523.5 -291.5,-523.5 -291.5,-1133.5 1284,-1133.5 ; 2173,-1133.5 2173,-523.5 ; 3440,-726.83 3440,-523.5 ; 4280,-726.83 4280,-523.5 ; 4902,-1140 4902,-937.17
  text "ALL ARTWORK VIEWED FROM TOP SIDE" at -228.5,-655.67 h60
  text "BOARD #:" at 2248,-655.67 h60
  text ".PRJ_Number" at 2793.5,-655.67 h60
  text "REV:" at 3638,-655.67 h60
  text ".PCB_Rev" at 3929.5,-655.67 h60
  text "SVN REV:" at 4476,-655.67 h60
  text ".VersionControl_RevNumber" at 4982,-655.67 h60
  text "LAYER NAME =" at -228.5,-858.49 h60
  text "PLOT NAME =" at -228.5,-1064.34 h60
  text ".plot_File_Name" at 577,-1064.34 h60
  text "GENERATED    :" at 2250,-1064.34 h60
  text ".Print_Date" at 3119.5,-1064.34 h60
  text ".Print_Time" at 3848.5,-1064.34 h60
  text "TEXAS INSTRUMENTS" at 5113,-1064.34 h60
M12 Stackup:
  lines w6: 11360,7460 13910,7460 ; 11360,7564.4 13910,7564.4 ; 11300,6975 ccw(c11334,6975) 11334,6941 13936,6941 ccw(c13936,6975) 13970,6975 13970,7681 ccw(c13936,7681) 13936,7715 11334,7715 ccw(c11334,7681) 11300,7681 11300,6975
  text "Layer Stack Up Detail for: Ref_Design.PcbDoc" at 11360,7597.1 h57
  text "Layer" at 11360,7525.4 h24
  text "Gerber" at 12255.81,7525.4 h24
  text "Copper" at 12819.33,7525.4 h24
  text "Dielectric" at 13422.04,7525.4 h24
  text "Name" at 11360,7477.4 h24
  text "Document" at 12255.81,7477.4 h24
  text "Thickness" at 12819.33,7477.4 h24
  text "Material" at 13422.04,7477.4 h24
  text "Top Solder Mask" at 11360,7384.44 h34
  text "(.GTS)" at 12255.81,7384.44 h34
  text "Solder Resist" at 13422.04,7384.44 h34
  text "Top Layer" at 11360,7287.69 h34
  text "(.GTL)" at 12255.81,7287.69 h34
  text "1.4mil" at 12819.33,7287.69 h34
  text "FR-4" at 13422.04,7239.31 h34
  text "Bottom Layer" at 11360,7190.94 h34
  text "(.GBL)" at 12255.81,7190.94 h34
  text "1.4mil" at 12819.33,7190.94 h34
  text "Bottom Solder Mask" at 11360,7094.19 h34
  text "(.GBS)" at 12255.81,7094.19 h34
  text "Solder Resist" at 13422.04,7094.19 h34
  text ".Layer_Name" at 577,-858.49 h60
M13 Component Bodies Top:
  text ".Layer_Name" at 577,-858.49 h60
M14 Component Bodies Bottom:
  text ".Layer_Name" at 577,-858.49 h60
M15 Courtyards Top:
  text ".Layer_Name" at 577,-858.49 h60
M16 Courtyards Bottom:
  text ".Layer_Name" at 577,-858.49 h60
Drill Drawing:
  text ".legend" at 2522.5,215.5 h60
  text "Drill Table" at 2547.5,30.5 h60
  text ".Layer_Name" at 577,-858.49 h60

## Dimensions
0,0 to 0,1500 on M2 Board Dimensions
0,0 to 2350,0 on M2 Board Dimensions
0,-410.5 to 1000,-410.5 on M2 Board Dimensions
